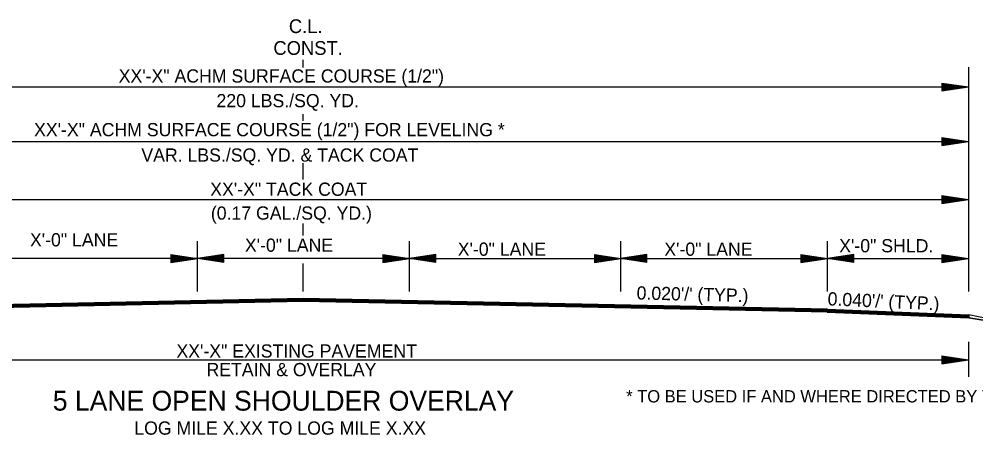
# Model space of a CAD drawing. Extents: x 542112 to 1930787, y -1968972 to 596640.
# Drawn here: x 546716 to 547259, y -1967239 to -1967003 of the extents above; entities that cross this region are included whole.
import ezdxf

# ---------------------------------------------------------------- set-up
doc = ezdxf.new("R2010")
doc.units = 0
doc.layers.add('R_Border Prem', color=7, linetype='Continuous')
doc.layers.add('R_Draft', color=7, linetype='Continuous')

msp = doc.modelspace()

# ---------------------------------------------------------------- linework, layer by layer
at = {"layer": 'R_Draft'}
for p, q in [((546876.84, -1967031), (546876.84, -1967026.59)), ((546496.65, -1967041.98), (547254.3, -1967041.98)), ((547239.3, -1967039.73), (547254.3, -1967041.98)), ((547239.3, -1967039.73), (547239.3, -1967044.23)), ((547239.3, -1967040.1), (547251.8, -1967041.98)), ((547239.3, -1967040.49), (547249.22, -1967041.98)), ((547239.3, -1967040.86), (547246.72, -1967041.98)), ((547239.3, -1967041.25), (547244.18, -1967041.98)), ((547239.3, -1967041.63), (547241.67, -1967041.98)), ((547239.3, -1967044.23), (547254.3, -1967041.98)), ((547239.3, -1967042.71), (547244.18, -1967041.98)), ((547239.3, -1967043.47), (547249.22, -1967041.98)), ((547239.3, -1967043.85), (547251.8, -1967041.98)), ((547239.3, -1967043.1), (547246.72, -1967041.98)), ((547239.3, -1967042.33), (547241.67, -1967041.98)), ((546876.84, -1967061.13), (546876.84, -1967057.46)), ((547239.3, -1967070.6), (547254.3, -1967072.85)), ((547239.3, -1967070.6), (547239.3, -1967075.1)), ((547239.3, -1967070.97), (547251.8, -1967072.85)), ((547239.3, -1967071.36), (547249.22, -1967072.85)), ((546496.65, -1967072.85), (547254.3, -1967072.85)), ((547239.3, -1967071.73), (547246.72, -1967072.85)), ((547239.3, -1967072.12), (547244.18, -1967072.85)), ((547239.3, -1967072.5), (547241.67, -1967072.85)), ((547239.3, -1967075.1), (547254.3, -1967072.85)), ((547239.3, -1967073.58), (547244.18, -1967072.85)), ((547239.3, -1967074.34), (547249.22, -1967072.85)), ((547239.3, -1967074.72), (547251.8, -1967072.85)), ((547239.3, -1967073.97), (547246.72, -1967072.85)), ((547239.3, -1967073.2), (547241.67, -1967072.85)), ((546876.84, -1967094.49), (546876.84, -1967085.18)), ((547239.3, -1967103.53), (547254.3, -1967105.78)), ((547239.3, -1967103.53), (547239.3, -1967108.03)), ((547239.3, -1967103.9), (547251.8, -1967105.78)), ((546496.65, -1967105.78), (547254.3, -1967105.78)), ((547239.3, -1967104.29), (547249.22, -1967105.78)), ((547239.3, -1967104.66), (547246.72, -1967105.78)), ((547239.3, -1967105.05), (547244.18, -1967105.78)), ((547239.3, -1967105.43), (547241.67, -1967105.78)), ((547239.3, -1967108.03), (547254.3, -1967105.78)), ((547239.3, -1967106.51), (547244.18, -1967105.78)), ((547239.3, -1967107.27), (547249.22, -1967105.78)), ((547239.3, -1967107.65), (547251.8, -1967105.78)), ((547239.3, -1967106.9), (547246.72, -1967105.78)), ((547239.3, -1967106.13), (547241.67, -1967105.78)), ((546876.84, -1967126.2), (546876.84, -1967119.55)), ((546816.84, -1967139.32), (546816.84, -1967129.42)), ((546816.84, -1967157.97), (546816.84, -1967129.42)), ((546937.1, -1967157.97), (546937.1, -1967129.42)), ((547057.1, -1967157.97), (547057.1, -1967129.42)), ((547174.3, -1967139.32), (547174.3, -1967129.42)), ((547174.3, -1967157.97), (547174.3, -1967129.42)), ((546816.84, -1967139.32), (546696.91, -1967139.32)), ((546801.84, -1967137.07), (546816.84, -1967139.32)), ((546801.84, -1967137.07), (546801.84, -1967141.57)), ((546801.84, -1967137.44), (546814.33, -1967139.32)), ((546801.84, -1967137.82), (546811.75, -1967139.32)), ((546801.84, -1967138.2), (546809.25, -1967139.32)), ((546801.84, -1967138.59), (546806.71, -1967139.32)), ((546801.84, -1967138.96), (546804.21, -1967139.32)), ((546801.84, -1967141.57), (546816.84, -1967139.32)), ((546801.84, -1967140.05), (546806.71, -1967139.32)), ((546801.84, -1967140.81), (546811.75, -1967139.32)), ((546801.84, -1967141.19), (546814.33, -1967139.32)), ((546801.84, -1967140.43), (546809.25, -1967139.32)), ((546801.84, -1967139.67), (546804.21, -1967139.32)), ((546816.84, -1967157.97), (546816.84, -1967139.32)), ((546937.1, -1967139.32), (546816.84, -1967139.32)), ((546816.84, -1967154.72), (546816.84, -1967141.43)), ((546831.91, -1967137.07), (546816.91, -1967139.32)), ((546831.91, -1967141.57), (546816.91, -1967139.32)), ((546831.91, -1967137.44), (546819.41, -1967139.32)), ((546831.91, -1967141.19), (546819.41, -1967139.32)), ((546831.91, -1967137.82), (546821.99, -1967139.32)), ((546831.91, -1967140.81), (546821.99, -1967139.32)), ((546831.91, -1967138.2), (546824.49, -1967139.32)), ((546831.91, -1967140.43), (546824.49, -1967139.32)), ((546831.91, -1967138.58), (546827.03, -1967139.32)), ((546831.91, -1967140.04), (546827.03, -1967139.32)), ((546831.91, -1967138.96), (546829.54, -1967139.32)), ((546831.91, -1967139.67), (546829.54, -1967139.32)), ((546831.91, -1967141.57), (546831.91, -1967137.07)), ((546922.1, -1967137.07), (546937.1, -1967139.32)), ((546922.1, -1967137.07), (546922.1, -1967141.57)), ((546922.1, -1967137.44), (546934.59, -1967139.32)), ((546922.1, -1967137.82), (546932.01, -1967139.32)), ((546922.1, -1967138.2), (546929.52, -1967139.32)), ((546922.1, -1967138.59), (546926.97, -1967139.32)), ((546922.1, -1967138.96), (546924.47, -1967139.32)), ((546922.1, -1967141.57), (546937.1, -1967139.32)), ((546922.1, -1967140.05), (546926.97, -1967139.32)), ((546922.1, -1967140.81), (546932.01, -1967139.32)), ((546922.1, -1967141.19), (546934.59, -1967139.32)), ((546922.1, -1967140.43), (546929.52, -1967139.32)), ((546922.1, -1967139.67), (546924.47, -1967139.32)), ((546952.1, -1967137.07), (546937.1, -1967139.32)), ((546937.1, -1967139.32), (547057.1, -1967139.32)), ((546952.1, -1967141.57), (546937.1, -1967139.32)), ((546952.1, -1967137.44), (546939.6, -1967139.32)), ((546952.1, -1967141.19), (546939.6, -1967139.32)), ((546952.1, -1967137.82), (546942.18, -1967139.32)), ((546952.1, -1967140.81), (546942.18, -1967139.32)), ((546952.1, -1967138.2), (546944.68, -1967139.32)), ((546952.1, -1967140.43), (546944.68, -1967139.32)), ((546952.1, -1967138.58), (546947.22, -1967139.32)), ((546952.1, -1967140.04), (546947.22, -1967139.32)), ((546952.1, -1967138.96), (546949.73, -1967139.32)), ((546952.1, -1967139.67), (546949.73, -1967139.32)), ((546952.1, -1967141.57), (546952.1, -1967137.07)), ((547042.1, -1967137.07), (547057.1, -1967139.32)), ((547042.1, -1967137.07), (547042.1, -1967141.57)), ((547042.1, -1967137.44), (547054.59, -1967139.32)), ((547042.1, -1967137.82), (547052.01, -1967139.32)), ((547042.1, -1967138.2), (547049.52, -1967139.32)), ((547042.1, -1967138.59), (547046.97, -1967139.32)), ((547042.1, -1967138.96), (547044.47, -1967139.32)), ((547042.1, -1967141.57), (547057.1, -1967139.32)), ((547042.1, -1967140.05), (547046.97, -1967139.32)), ((547042.1, -1967140.81), (547052.01, -1967139.32)), ((547042.1, -1967141.19), (547054.59, -1967139.32)), ((547042.1, -1967140.43), (547049.52, -1967139.32)), ((547042.1, -1967139.67), (547044.47, -1967139.32)), ((547054.3, -1967139.32), (547174.3, -1967139.32)), ((547071.91, -1967137.07), (547056.91, -1967139.32)), ((547071.91, -1967141.57), (547056.91, -1967139.32)), ((547071.91, -1967137.44), (547059.41, -1967139.32)), ((547071.91, -1967141.19), (547059.41, -1967139.32)), ((547071.91, -1967137.82), (547061.99, -1967139.32)), ((547071.91, -1967140.81), (547061.99, -1967139.32)), ((547071.91, -1967138.2), (547064.49, -1967139.32)), ((547071.91, -1967140.43), (547064.49, -1967139.32)), ((547071.91, -1967138.58), (547067.03, -1967139.32)), ((547071.91, -1967140.04), (547067.03, -1967139.32)), ((547071.91, -1967138.96), (547069.54, -1967139.32)), ((547071.91, -1967139.67), (547069.54, -1967139.32)), ((547071.91, -1967141.57), (547071.91, -1967137.07)), ((547159.3, -1967137.07), (547174.3, -1967139.32)), ((547159.3, -1967137.07), (547159.3, -1967141.57)), ((547159.3, -1967137.44), (547171.8, -1967139.32)), ((547159.3, -1967137.82), (547169.22, -1967139.32)), ((547159.3, -1967138.2), (547166.72, -1967139.32)), ((547159.3, -1967138.59), (547164.18, -1967139.32)), ((547159.3, -1967138.96), (547161.67, -1967139.32)), ((547159.3, -1967141.57), (547174.3, -1967139.32)), ((547159.3, -1967140.05), (547164.18, -1967139.32)), ((547159.3, -1967140.81), (547169.22, -1967139.32)), ((547159.3, -1967141.19), (547171.8, -1967139.32)), ((547159.3, -1967140.43), (547166.72, -1967139.32)), ((547159.3, -1967139.67), (547161.67, -1967139.32)), ((547189.3, -1967137.07), (547174.3, -1967139.32)), ((547174.3, -1967139.32), (547254.3, -1967139.32)), ((547189.3, -1967141.57), (547174.3, -1967139.32)), ((547189.3, -1967137.44), (547176.81, -1967139.32)), ((547189.3, -1967141.19), (547176.81, -1967139.32)), ((547189.3, -1967137.82), (547179.39, -1967139.32)), ((547189.3, -1967140.81), (547179.39, -1967139.32)), ((547189.3, -1967138.2), (547181.88, -1967139.32)), ((547189.3, -1967140.43), (547181.88, -1967139.32)), ((547189.3, -1967138.58), (547184.43, -1967139.32)), ((547189.3, -1967140.04), (547184.43, -1967139.32)), ((547189.3, -1967138.96), (547186.93, -1967139.32)), ((547189.3, -1967139.67), (547186.93, -1967139.32)), ((547189.3, -1967141.57), (547189.3, -1967137.07)), ((547239.3, -1967137.07), (547254.3, -1967139.32)), ((547239.3, -1967137.07), (547239.3, -1967141.57)), ((547239.3, -1967137.44), (547251.8, -1967139.32)), ((547239.3, -1967137.82), (547249.22, -1967139.32)), ((547239.3, -1967138.2), (547246.72, -1967139.32)), ((547239.3, -1967138.59), (547244.18, -1967139.32)), ((547239.3, -1967138.96), (547241.67, -1967139.32)), ((547239.3, -1967141.57), (547254.3, -1967139.32)), ((547239.3, -1967140.05), (547244.18, -1967139.32)), ((547239.3, -1967140.81), (547249.22, -1967139.32)), ((547239.3, -1967141.19), (547251.8, -1967139.32)), ((547239.3, -1967140.43), (547246.72, -1967139.32)), ((547239.3, -1967139.67), (547241.67, -1967139.32)), ((546876.84, -1967157.97), (546876.84, -1967142.12)), ((546876.84, -1967162.1), (546576.91, -1967168.1)), ((546876.84, -1967162.4), (546576.92, -1967168.4)), ((546876.85, -1967162.7), (546576.92, -1967168.7)), ((546876.85, -1967163), (546576.93, -1967169)), ((546876.86, -1967163.3), (546576.93, -1967169.3)), ((546876.87, -1967163.6), (546576.94, -1967169.6)), ((547174.28, -1967169.25), (546876.81, -1967163.3)), ((547174.27, -1967169.55), (546876.81, -1967163.6)), ((547174.29, -1967168.65), (546876.82, -1967162.7)), ((547174.28, -1967168.95), (546876.82, -1967163)), ((547174.29, -1967168.35), (546876.83, -1967162.4)), ((547174.3, -1967168.05), (546876.84, -1967162.1)), ((546876.87, -1967163.8), (546576.94, -1967169.8)), ((547174.27, -1967169.75), (546876.8, -1967163.8)), ((547174.26, -1967168.95), (547254.56, -1967172.16)), ((547174.28, -1967168.65), (547254.54, -1967171.86)), ((547174.29, -1967168.35), (547254.55, -1967171.56)), ((547174.3, -1967168.05), (547254.56, -1967171.26)), ((547174.23, -1967169.75), (547254.56, -1967172.96)), ((547174.24, -1967169.55), (547254.56, -1967172.76)), ((547174.25, -1967169.25), (547254.56, -1967172.46)), ((547254.56, -1967171.26), (547254.56, -1967172.96)), ((547293.8, -1967179.5), (547254.56, -1967171.26)), ((547254.56, -1967171.26), (547254.56, -1967172.96)), ((547254.56, -1967171.26), (547254.56, -1967172.96)), ((547354.63, -1967189.64), (547254.56, -1967172.96)), ((547254.56, -1967172.96), (547254.56, -1967172.96)), ((547254.56, -1967172.96), (547293.8, -1967179.5)), ((547254.3, -1967186.53), (547254.3, -1967206.53)), ((547239.3, -1967194.53), (547254.3, -1967196.78)), ((547239.3, -1967194.53), (547239.3, -1967199.03)), ((547239.3, -1967194.91), (547251.8, -1967196.78)), ((547239.3, -1967195.29), (547249.22, -1967196.78)), ((547239.3, -1967195.66), (547246.72, -1967196.78)), ((547239.3, -1967196.05), (547244.18, -1967196.78)), ((546496.65, -1967196.78), (547254.3, -1967196.78)), ((547239.3, -1967196.43), (547241.67, -1967196.78)), ((547239.3, -1967199.03), (547254.3, -1967196.78)), ((547239.3, -1967197.52), (547244.18, -1967196.78)), ((547239.3, -1967198.27), (547249.22, -1967196.78)), ((547239.3, -1967198.66), (547251.8, -1967196.78)), ((547239.3, -1967197.9), (547246.72, -1967196.78)), ((547239.3, -1967197.13), (547241.67, -1967196.78))]:
    msp.add_line(p, q, dxfattribs=at)
msp.add_lwpolyline([(547254.3, -1967030.72), (547254.3, -1967157.97)], dxfattribs=at)

# ---------------------------------------------------------------- texts
at = {"layer": 'R_Border Prem'}
msp.add_text('* TO BE USED IF AND WHERE DIRECTED BY THE ENGINEER.', height=7, dxfattribs=at).set_placement((547060.13, -1967221.03))
at = {"layer": 'R_Draft'}
for s, height, p in [('C.L.', 7.8, (546868.73, -1967011.39)), ('CONST.', 7.8, (546859.95, -1967023.75)), ('XX\'-X" ACHM SURFACE COURSE (1/2")', 7.5, (546772.18, -1967039.47)), ('220 LBS./SQ. YD. ', 7.5, (546827.66, -1967053.48)), ('XX\'-X" ACHM SURFACE COURSE (1/2") FOR LEVELING *', 7.5, (546724.17, -1967069.94)), ('VAR. LBS./SQ. YD. & TACK COAT', 7.5, (546785.05, -1967084.35)), ('XX\'-X" TACK COAT', 7.5, (546824.12, -1967103.74)), ('(0.17 GAL./SQ. YD.)', 7.5, (546824.47, -1967117.28)), ('X\'-0" LANE', 7.5, (546721.84, -1967132.45)), ('X\'-0" LANE', 7.5, (546843.79, -1967135.48)), ('X\'-0" LANE', 7.5, (546964.55, -1967137.77)), ('X\'-0" LANE', 7.5, (547081.75, -1967137.77)), ('X\'-0" SHLD.', 7.5, (547180.99, -1967135.83)), ('XX\'-X" EXISTING PAVEMENT', 7.5, (546804.95, -1967195.56)), ('RETAIN & OVERLAY', 7.5, (546821.99, -1967206.11)), ('5 LANE OPEN SHOULDER OVERLAY', 11.25, (546734.8, -1967225.66)), ('LOG MILE X.XX TO LOG MILE X.XX', 7.5, (546781.04, -1967239.32))]:
    msp.add_text(s, height=height, dxfattribs=at).set_placement(p)
for s, rotation, p in [("0.020'/' (TYP.)", 358.6042, (547065.97, -1967162.55)), ("0.040'/' (TYP.)", 357.3634, (547174.28, -1967165.86))]:
    msp.add_text(s, height=7.5, rotation=rotation, dxfattribs=at).set_placement(p)

doc.saveas('drawing.dxf')
